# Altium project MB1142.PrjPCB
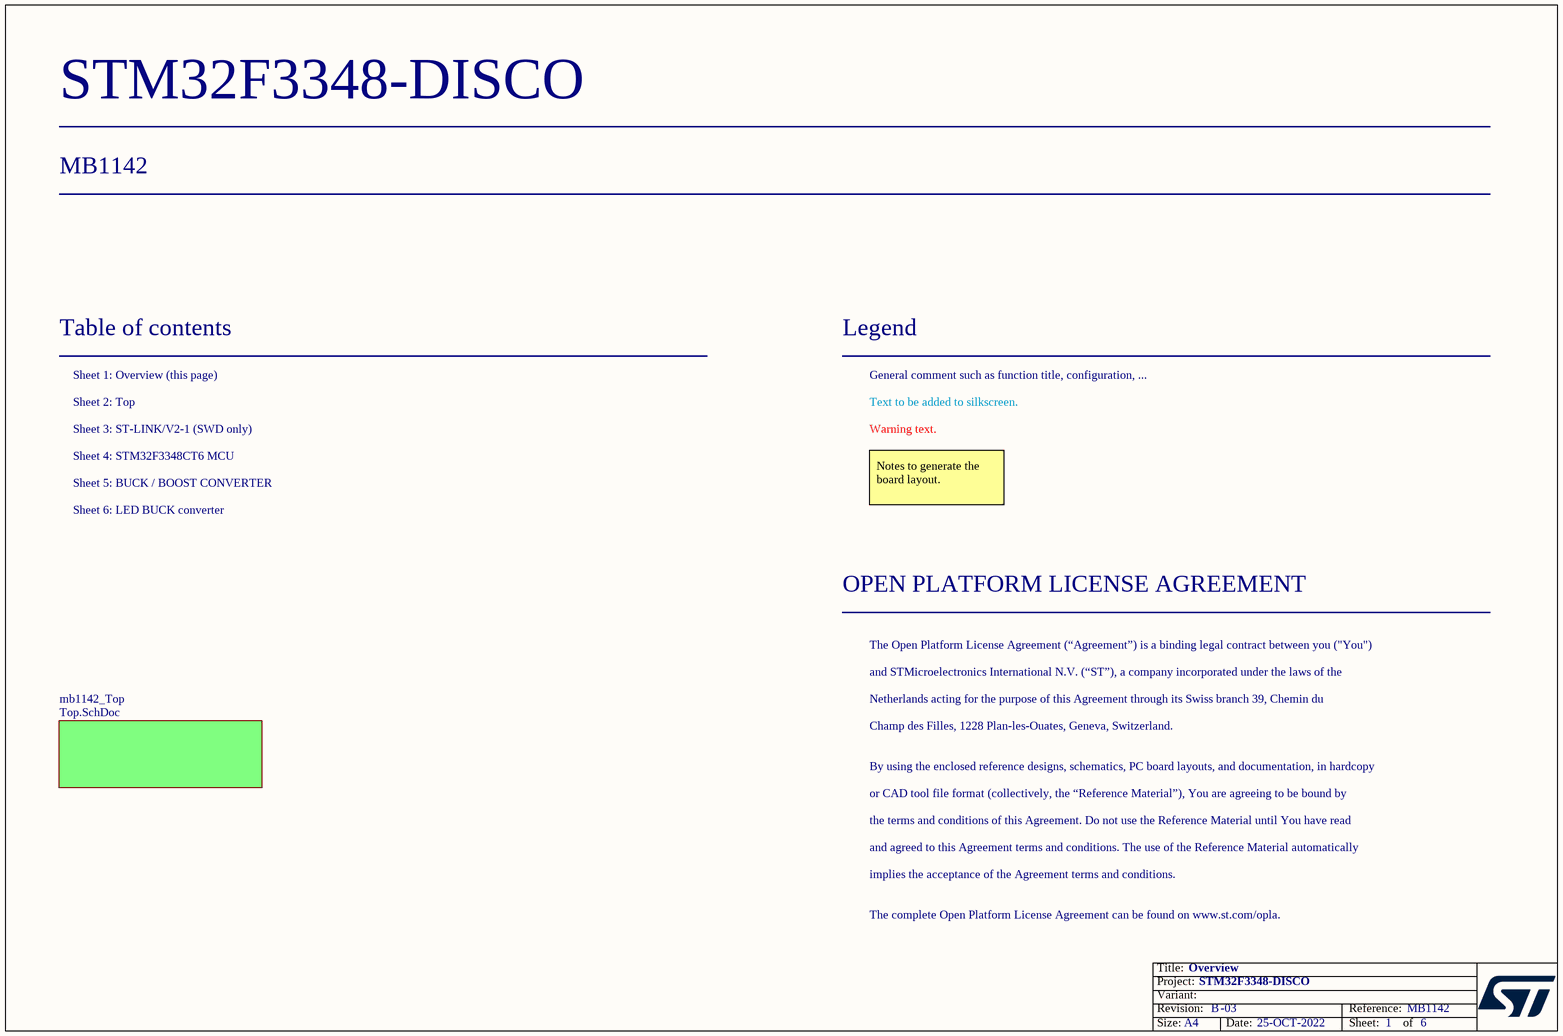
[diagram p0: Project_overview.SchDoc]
Board_Assembly_Revision: 03; Board_Document_Date: 25-OCT-2022; Board_Name: STM32F3348-DISCO; Board_PCB_Revision: B; Board_Reference: MB1142
6 sheets, 188 parts. Net scope: flat (ports and power ports of the same name join across sheets).
Sheets:
  Project_overview.SchDoc
    mb1142_Top = Top.SchDoc
      U_ST_LINK = ST_LINK_V2.SCHDOC
      U_STM32Fx = STM32Fx.SchDoc
      U_BUCK_BOOST = BUCK_BOOST.SchDoc
      U_BUCK_LED = BUCK_LED.SchDoc

## Sheet Project_overview.SchDoc: Overview
size A4; Date: Not used; ApprovedBy: Not used; CheckedBy: Not used; Author: Not used; CompanyName: STMicroelectronics; DrawnBy: Not used; Engineer: Not used; Organization: Not used; Address1: Not used; Address2: Not used; Address3: Not used; Address4: Not used; DocumentNumber: Not used; Revision: Not used; SheetNumber: 1; SheetTotal: 6

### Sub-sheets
mb1142_Top = Top.SchDoc: no entries

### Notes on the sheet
- Table of contents
- Sheet 1: Overview (this page)
- Legend
- General comment such as function title, configuration, ...
- Sheet 2: Top
- Sheet 3: ST-LINK/V2-1 (SWD only)
- Text to be added to silkscreen.
- Warning text.
- Sheet 4: STM32F3348CT6 MCU
- Sheet 6: LED BUCK converter
- Sheet 5: BUCK / BOOST CONVERTER
- Notes to generate the board layout.
- OPEN PLATFORM LICENSE AGREEMENT
- The Open Platform License Agreement (“Agreement”) is a binding legal contract between you ("You")
- and STMicroelectronics International N.V. (“ST”), a company incorporated under the laws of the
- Netherlands acting for the purpose of this Agreement through its Swiss branch 39, Chemin du
- Champ des Filles, 1228 Plan-les-Ouates, Geneva, Switzerland.
- By using the enclosed reference designs, schematics, PC board layouts, and documentation, in hardcopy
- or CAD tool file format (collectively, the “Reference Material”), You are agreeing to be bound by
- the terms and conditions of this Agreement. Do not use the Reference Material until You have read
- and agreed to this Agreement terms and conditions. The use of the Reference Material automatically
- implies the acceptance of the Agreement terms and conditions.
- The complete Open Platform License Agreement can be found on www.st.com/opla.

## Sheet Top.SchDoc: TOP
size A4; CompanyName: STM; DocumentNumber: MB1142; Revision: B-02; SheetNumber: 2; SheetTotal: 6; PageSetup: Record=PageOptions¦CenterHorizontal=True¦CenterVertical=True¦PrintScale=-0.03¦XCorrection=1.00¦YCorrection=1.00¦PrintKind=0¦BorderSize=5000000¦LeftOffset=0¦BottomOffset=0¦Orientation=2¦PaperLength=1000¦PaperWidth=1000¦Scale=100¦PaperSource=15¦PrintQuality=1200¦MediaType=1¦DitherType=10¦PaperKind=A4¦PrintScaleMode=1; Project: STM32F3348-DISCO
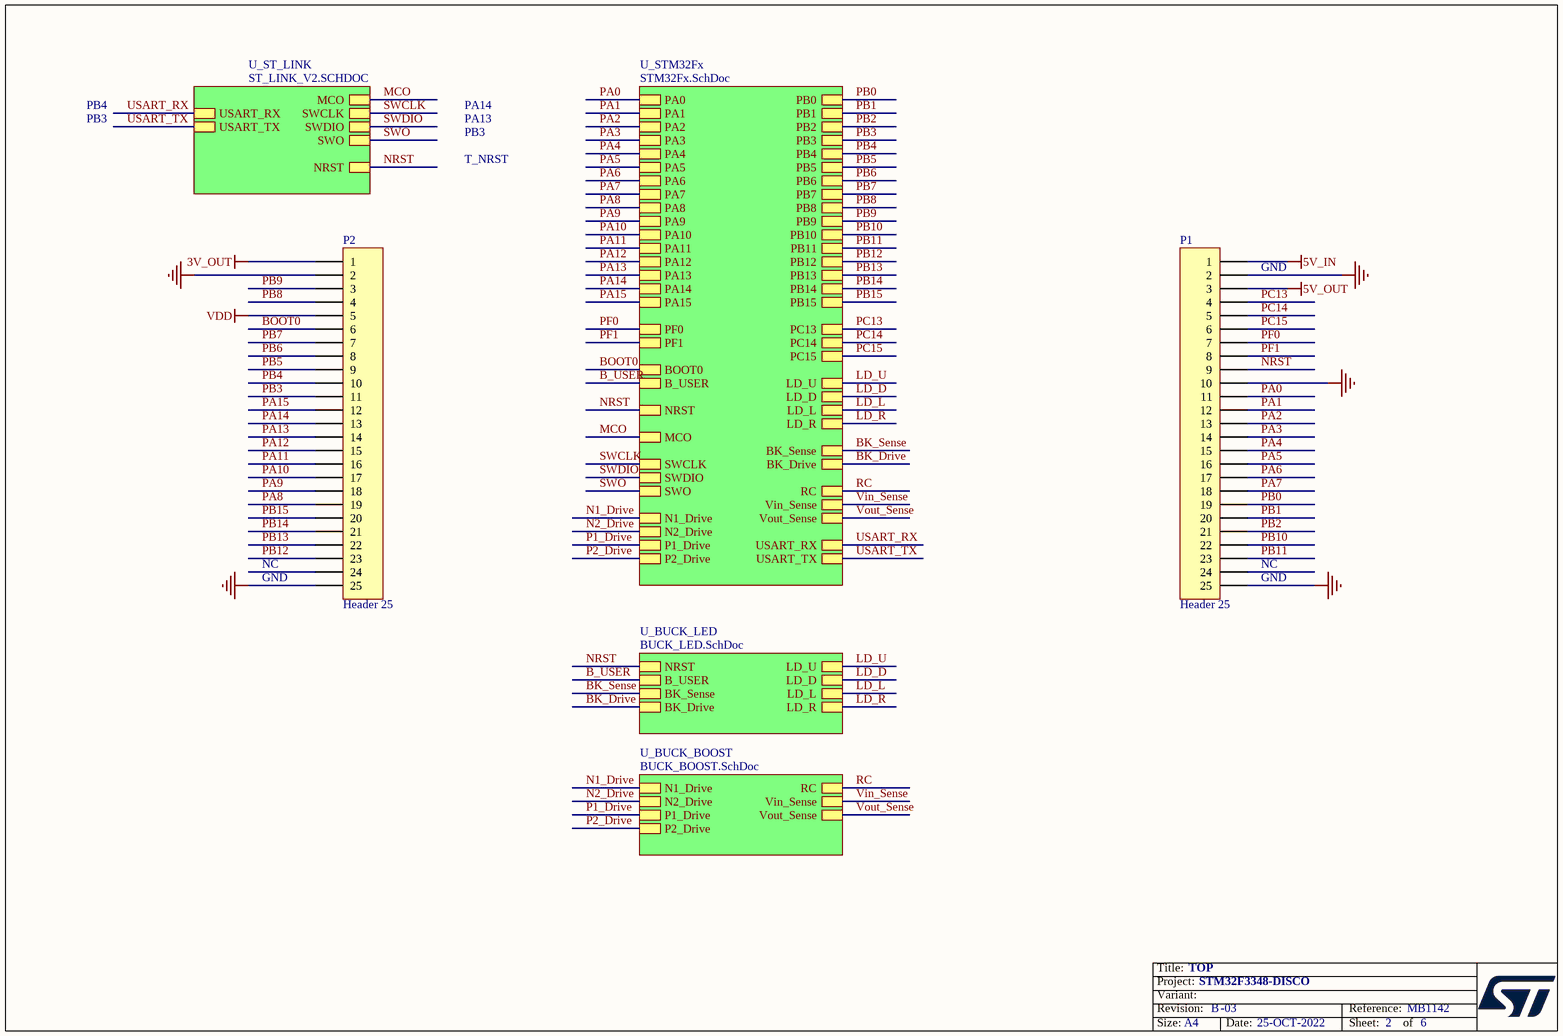
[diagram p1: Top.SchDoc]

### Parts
P1  Header 25  [HDR1X25]
P2  Header 25  [HDR1X25]

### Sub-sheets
U_BUCK_BOOST = BUCK_BOOST.SchDoc: N1_Drive, N2_Drive, Vout_Sense, P1_Drive, P2_Drive, Vin_Sense, RC
U_BUCK_LED = BUCK_LED.SchDoc: NRST, B_USER, BK_Sense, BK_Drive, LD_D, LD_U, LD_L, LD_R
U_ST_LINK = ST_LINK_V2.SCHDOC: NRST, MCO, SWDIO, SWCLK, SWO, USART_RX, USART_TX
U_STM32Fx = STM32Fx.SchDoc: PB8, BOOT0, NRST, PC15, PC14, PF1, PF0, MCO, PC13, PA0, PA1, PA2, PA3, PA4, PA5, PA6, PA7, PA8, PA9, PA10, PA11, PA12, PA13, PA14, PA15, PB0, PB1, PB2, PB3, PB4, PB5, PB6, PB7, PB9, PB10, PB11, PB12, PB13, PB14, PB15, B_USER, LD_D, LD_U, LD_L, LD_R, RC, Vout_Sense, P2_Drive, BK_Sense, Vin_Sense, BK_Drive, N1_Drive, P1_Drive, N2_Drive, SWCLK, SWDIO, SWO, USART_TX, USART_RX

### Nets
3V_OUT: P2.1  [project net 3V]
5V_IN: P1.1
5V_OUT: P1.3
GND: P1.2 P1.10 P1.25 P2.2 P2.25
VDD: P2.5
B_USER: sheet U_STM32Fx/B_USER, sheet U_BUCK_LED/B_USER
BK_Drive: sheet U_STM32Fx/BK_Drive, sheet U_BUCK_LED/BK_Drive
BK_Sense: sheet U_STM32Fx/BK_Sense, sheet U_BUCK_LED/BK_Sense
BOOT0: P2.6 ; sheet U_STM32Fx/BOOT0
LD_D: sheet U_STM32Fx/LD_D, sheet U_BUCK_LED/LD_D
LD_L: sheet U_STM32Fx/LD_L, sheet U_BUCK_LED/LD_L
LD_R: sheet U_STM32Fx/LD_R, sheet U_BUCK_LED/LD_R
LD_U: sheet U_STM32Fx/LD_U, sheet U_BUCK_LED/LD_U
MCO: sheet U_ST_LINK/MCO, sheet U_STM32Fx/MCO
N1_Drive: sheet U_STM32Fx/N1_Drive, sheet U_BUCK_BOOST/N1_Drive
N2_Drive: sheet U_STM32Fx/N2_Drive, sheet U_BUCK_BOOST/N2_Drive
NRST: P1.9 ; sheet U_ST_LINK/NRST, sheet U_STM32Fx/NRST, sheet U_BUCK_LED/NRST
P1_Drive: sheet U_STM32Fx/P1_Drive, sheet U_BUCK_BOOST/P1_Drive
P2_Drive: sheet U_STM32Fx/P2_Drive, sheet U_BUCK_BOOST/P2_Drive
PA0: P1.11 ; sheet U_STM32Fx/PA0
PA1: P1.12 ; sheet U_STM32Fx/PA1
PA2: P1.13 ; sheet U_STM32Fx/PA2
PA3: P1.14 ; sheet U_STM32Fx/PA3
PA4: P1.15 ; sheet U_STM32Fx/PA4
PA5: P1.16 ; sheet U_STM32Fx/PA5
PA6: P1.17 ; sheet U_STM32Fx/PA6
PA7: P1.18 ; sheet U_STM32Fx/PA7
PA8: P2.19 ; sheet U_STM32Fx/PA8
PA9: P2.18 ; sheet U_STM32Fx/PA9
PA10: P2.17 ; sheet U_STM32Fx/PA10
PA11: P2.16 ; sheet U_STM32Fx/PA11
PA12: P2.15 ; sheet U_STM32Fx/PA12
PA13: P2.14 ; sheet U_STM32Fx/PA13
PA14: P2.13 ; sheet U_STM32Fx/PA14
PA15: P2.12 ; sheet U_STM32Fx/PA15
PB0: P1.19 ; sheet U_STM32Fx/PB0
PB1: P1.20 ; sheet U_STM32Fx/PB1
PB2: P1.21 ; sheet U_STM32Fx/PB2
PB3: P2.11 ; sheet U_STM32Fx/PB3
PB4: P2.10 ; sheet U_STM32Fx/PB4
PB5: P2.9 ; sheet U_STM32Fx/PB5
PB6: P2.8 ; sheet U_STM32Fx/PB6
PB7: P2.7 ; sheet U_STM32Fx/PB7
PB8: P2.4 ; sheet U_STM32Fx/PB8
PB9: P2.3 ; sheet U_STM32Fx/PB9
PB10: P1.22 ; sheet U_STM32Fx/PB10
PB11: P1.23 ; sheet U_STM32Fx/PB11
PB12: P2.23 ; sheet U_STM32Fx/PB12
PB13: P2.22 ; sheet U_STM32Fx/PB13
PB14: P2.21 ; sheet U_STM32Fx/PB14
PB15: P2.20 ; sheet U_STM32Fx/PB15
PC13: P1.4 ; sheet U_STM32Fx/PC13
PC14: P1.5 ; sheet U_STM32Fx/PC14
PC15: P1.6 ; sheet U_STM32Fx/PC15
PF0: P1.7 ; sheet U_STM32Fx/PF0
PF1: P1.8 ; sheet U_STM32Fx/PF1
RC: sheet U_STM32Fx/RC, sheet U_BUCK_BOOST/RC
SWCLK: sheet U_ST_LINK/SWCLK, sheet U_STM32Fx/SWCLK
SWDIO: sheet U_ST_LINK/SWDIO, sheet U_STM32Fx/SWDIO
SWO: sheet U_ST_LINK/SWO, sheet U_STM32Fx/SWO
USART_RX: sheet U_ST_LINK/USART_RX, sheet U_STM32Fx/USART_RX
USART_TX: sheet U_ST_LINK/USART_TX, sheet U_STM32Fx/USART_TX
Vin_Sense: sheet U_STM32Fx/Vin_Sense, sheet U_BUCK_BOOST/Vin_Sense
Vout_Sense: sheet U_STM32Fx/Vout_Sense, sheet U_BUCK_BOOST/Vout_Sense

Not connected (* = marked no-connect by the designer): P1 24; P2 24

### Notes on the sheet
- PB4
- PA14
- PB3
- PA13
- T_NRST
- (near P1) GND
- GND
- NC
- (near P1) NC

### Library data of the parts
P1 P2 = Header 25: Header, 25-Pin

## Sheet ST_LINK_V2.SCHDOC: ST-LINK/V2-1 (SWD only)
size A4; CompanyName: STM; DocumentNumber: MB1142; Revision: B-02; SheetNumber: 3; SheetTotal: 6; PageSetup: Record=PageOptions¦CenterHorizontal=True¦CenterVertical=True¦PrintScale=1.00¦XCorrection=1.00¦YCorrection=1.00¦PrintKind=0¦BorderSize=5000000¦LeftOffset=0¦BottomOffset=0¦Orientation=2¦PaperLength=1000¦PaperWidth=1000¦Scale=100¦PaperSource=7¦PrintQuality=-4¦MediaType=1¦DitherType=10¦PaperKind=A4¦PrintScaleMode=1; Project: STM32F3348-DISCO
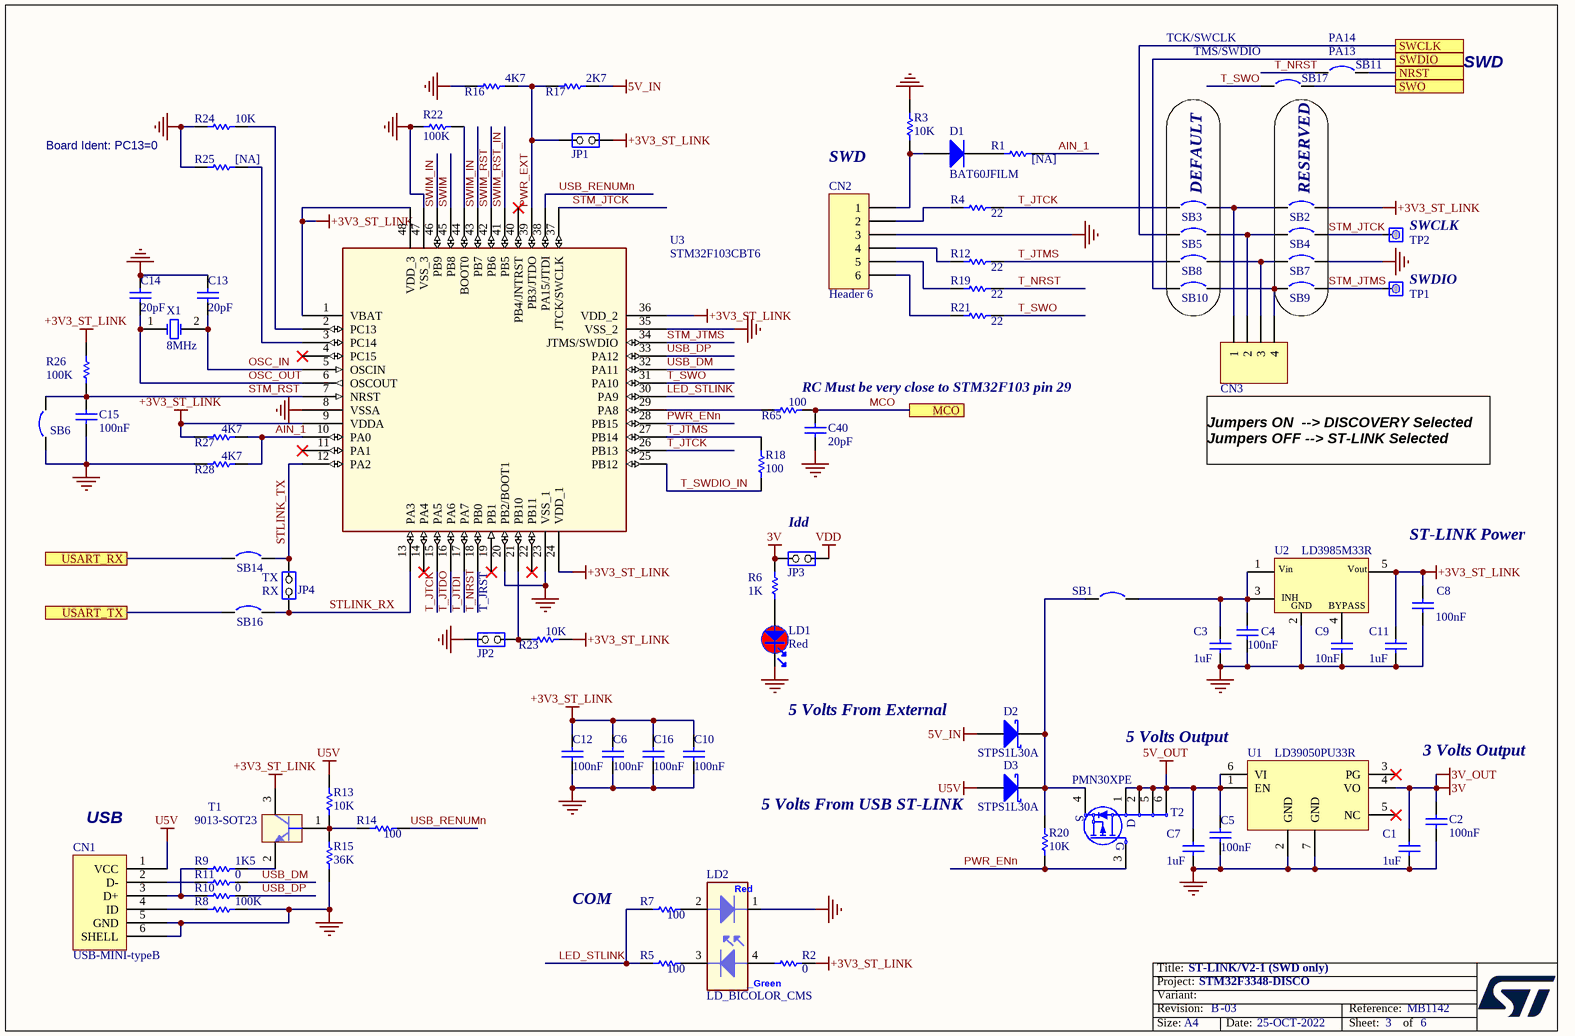
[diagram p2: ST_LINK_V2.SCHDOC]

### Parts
C1  1uF  [0603C]
C2  100nF  [0402C]
C3  1uF  [0603C]
C4  100nF  [0402C]
C5  100nF  [0402C]
C6  100nF  [0402C]
C7  1uF  [0603C]
C8  100nF  [0402C]
C9  10nF  [0603C]
C10  100nF  [0402C]
C11  1uF  [0603C]
C12  100nF  [0402C]
C13  20pF  [0402C]
C14  20pF  [0402C]
C15  100nF  [0402C]
C16  100nF  [0402C]
C40  20pF  [0402C]
CN1  USB-MINI-typeB  [USB-MINI-B-SMD]
CN2  Header 6  [HDR1X6]
CN3  Header 4  [Header 4]  (value not drawn)
D1  BAT60JFILM  [SOD323/A]
D2  STPS1L30A  [SMA]
D3  STPS1L30A  [SMA]
JP1  JP2  [SIP2/2.54]  (value not drawn)
JP2  Jumper2  [SIP2/2.54]  (value not drawn)
JP3  Jumper2  [SIP2/2.54]  (value not drawn)
JP4  Jumper2  [SIP2/2.54]  (value not drawn)
LD1  value Red  [LED_0603_RED]  (hidden comment: LED_red)
LD2  LD_BICOLOR_CMS  [HSMF-A201]
R1  [NA]  [0402R]
R2  0  [0402R]
R3  10K  [0402R]
R4  22  [0402R]
R5  100  [0402R]
R6  1K  [0402R]
R7  100  [0402R]
R8  100K  [0402R]
R9  1K5  [0402R]
R10  0  [0402R]
R11  0  [0402R]
R12  22  [0402R]
R13  10K  [0402R]
R14  100  [0402R]
R15  36K  [0402R]
R16  4K7  [0402R]
R17  2K7  [0402R]
R18  100  [0402R]
R19  22  [0402R]
R20  10K  [0402R]
R21  22  [0402R]
R22  100K  [0402R]
R23  10K  [0402R]
R24  10K  [0402R]
R25  [NA]  [0402R]
R26  100K  [0402R]
R27  4K7  [0402R]
R28  4K7  [0402R]
R65  100  [0402R]
SB1  Circuit Breaker  [JP2_SMD]  (value not drawn)
SB2  Circuit Breaker  [JP2_SMD]  (value not drawn)
SB3  Circuit Breaker  [JP2_SMD]  (value not drawn)
SB4  Circuit Breaker  [JP2_SMD]  (value not drawn)
SB5  Circuit Breaker  [JP2_SMD]  (value not drawn)
SB6  Circuit Breaker  [JP2_SMD]  (value not drawn)
SB7  Circuit Breaker  [JP2_SMD]  (value not drawn)
SB8  Circuit Breaker  [JP2_SMD]  (value not drawn)
SB9  Circuit Breaker  [JP2_SMD]  (value not drawn)
SB10  Circuit Breaker  [JP2_SMD]  (value not drawn)
SB11  Circuit Breaker  [JP2_SMD]  (value not drawn)
SB14  Circuit Breaker  [JP2_SMD]  (value not drawn)
SB16  Circuit Breaker  [JP2_SMD]  (value not drawn)
SB17  Circuit Breaker  [JP2_SMD]  (value not drawn)
T1  9013-SOT23  [SOT23]
T2  value PMN30XPE  [MOS_TSOP6_CASE-457_P095]  (hidden comment: PMN30XP)
TP1  Test point 1 pin with hole  [SIP1/2.54]  (value not drawn)
TP2  Test point 1 pin with hole  [SIP1/2.54]  (value not drawn)
U1  LD39050PU33R  [DFN6_3x3]
U2  LD3985M33R  [SOT-23-5L]
U3  STM32F103CBT6  [QFP48 7X7]
X1  8MHz  [XTAL1]

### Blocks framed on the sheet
DEFAULT: SB3 SB5 SB8 SB10
RESERVED: SB2 SB4 SB7 SB9

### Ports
MCO, NRST, SWCLK, SWDIO, SWO, USART_RX, USART_TX

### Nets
3V: C1.2 C2.2 JP3.1(COMMON) R6.2 U1.4(VO)  [also labelled 3V_OUT]
5V_IN: D2.1(A) R17.2
5V_OUT: C5.2 C7.2 T2.1(S) T2.2(S) T2.5(D) T2.6(D) U1.1(EN) U1.6(VI)
+3V3_ST_LINK: C6.2 C8.2 C10.2 C11.1 C12.2 C16.1 JP1.2(NO) R2.2 R23.2 R26.2 R27.1 SB2.2 T1.3(C) U2.5(Vout) U3.1(VBAT) U3.9(VDDA) U3.24(VDD_1) U3.36(VDD_2) U3.48(VDD_3)
GND: C1.1 C2.1 C3.1 C4.1 C5.1 C6.1 C7.1 C8.1 C9.1 C10.1 C11.2 C12.1 C13.1 C14.1 C15.1 C16.2 C40.2 CN1.5(GND) CN1.6(SHELL) CN2.3 JP2.1(COMMON) LD1.2 LD2.1 R3.2 R8.2 R15.1 R16.1 R22.1 R24.1 R25.1 R28.1 SB6.1 SB7.2 U1.2(GND) U1.7(GND) U2.2(GND) U3.8(VSSA) U3.20(PB2/BOOT1) U3.23(VSS_1) U3.35(VSS_2) U3.47(VSS_3)
U5V: CN1.1(VCC) D3.1(A) R13.2
VDD: JP3.2(NO)
AIN_1: R1.2 R27.2 R28.2 U3.10(PA0)
LED_STLINK: R5.1 R7.1 U3.30(PA9)
MCO: C40.1 R65.2 ; port MCO
NRST: SB11.2 ; port NRST
OSC_IN: C13.2 U3.5(OSCIN) X1.2(OSC2)
OSC_OUT: C14.2 U3.6(OSCOUT) X1.1(OSC1)
PA13: SB10.1 ; port SWDIO
PA14: SB5.1 ; port SWCLK
PB3: SB16.1 SB17.2 ; port SWO, port USART_TX
PB4: SB14.1 ; port USART_RX
PWR_ENn: R20.1 T2.3(G) U3.28(PB15)
PWR_EXT: JP1.1(COMMON) R16.2 R17.1 U3.39(PB3/JTDO)
STLINK_RX: JP4.1(COMMON) SB16.2 U3.13(PA3)
STLINK_TX: JP4.2(NO) SB14.2 U3.12(PA2)
STM_JTCK: SB4.2 TP2.1(COMMON) U3.37(JTCK/SWCLK)
STM_JTMS: SB9.2 TP1.1(COMMON) U3.34(JTMS/SWDIO)
STM_RST: C15.2 R26.1 SB6.2 U3.7(NRST)
SWIM: U3.45(PB8)
SWIM_IN: U3.43(PB7) U3.46(PB9)
SWIM_RST: U3.42(PB6)
SWIM_RST_IN: U3.41(PB5)
T_JTCK: R4.2 SB3.1 U3.15(PA5) U3.26(PB13)
T_JTDI: U3.17(PA7)
T_JTDO: U3.16(PA6)
T_JTMS: R12.2 R18.2 SB8.1 U3.27(PB14)
T_NRST: R19.2 SB11.1 U3.18(PB0)
T_SWDIO_IN: R18.1 U3.25(PB12)
T_SWO: R21.2 SB17.1 U3.31(PA10)
USB_DM: R11.2 U3.32(PA11)
USB_DP: R10.2 U3.33(PA12)
USB_RENUMn: R14.2 U3.38(PA15/JTDI)
NetC3_2: C3.2 C4.2 SB1.2 U2.1(Vin) U2.3(CE)
NetC9_2: C9.2 U2.4(BYPASS)
NetCN1_2: CN1.2(D-) R11.1
NetCN1_3: CN1.3(D+) R9.1 R10.1
NetCN1_4: CN1.4(ID) R8.1
NetCN2_1: CN2.1 D1.1(A) R3.1
NetCN2_2: CN2.2 R4.1
NetCN2_4: CN2.4 R12.1
NetCN2_5: CN2.5 R19.1
NetCN2_6: CN2.6 R21.1
NetCN3_1: CN3.1 SB2.1 SB3.2
NetCN3_2: CN3.2 SB4.1 SB5.2
NetCN3_3: CN3.3 SB7.1 SB8.2
NetCN3_4: CN3.4 SB9.1 SB10.2
NetD1_2: D1.2(K) R1.1
NetD2_2: D2.2(K) D3.2(K) R20.2 SB1.1 T2.4(S)
NetJP2_2: JP2.2(NO) R23.1 U3.21(PB10)
NetLD1_1: LD1.1 R6.1
NetLD2_2: LD2.2 R7.2
NetLD2_3: LD2.3 R5.2
NetLD2_4: LD2.4 R2.1
NetR9_2: R9.2 T1.2(E)
NetR13_1: R13.1 R14.1 R15.2 T1.1(B)
NetR22_2: R22.2 U3.44(BOOT0)
NetR24_2: R24.2 U3.2(PC13)
NetR25_2: R25.2 U3.3(PC14)
NetR65_1: R65.1 U3.29(PA8)

Not connected (* = marked no-connect by the designer): U1 3(PG)* 5(NC)*; U3 4(PC15)* 11(PA1)* 14(PA4)* 19(PB1)* 22(PB11)* 40(PB4/JNTRST)*

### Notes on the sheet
- TCK/SWCLK
- (near SB11) PA14
- (near SB17) TMS/SWDIO
- (near SB11) PA13
- SWD
- Board Ident: PC13=0
- (near TP2) SWCLK
- (near TP1) SWDIO
- (near R65) RC Must be very close to STM32F103 pin 29
- Jumpers ON  --> DISCOVERY Selected
  Jumpers OFF --> ST-LINK Selected
- TX
- Idd
- ST-LINK Power
- RX
- T_JRST
- 5 Volts From External
- (near U1) 5 Volts Output
- 3 Volts Output
- (near CN1) USB
- (near D3) 5 Volts From USB ST-LINK
- COM

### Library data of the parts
C1 C3 C7 C11 = Cap_1uF_X5R_10%_0603: Capacitor,1uF,16V,X5R,10%,0603,YAGEO; Manuf_Part_1: CC0603KRX5R7BB105
C2 C4-C6 C8 C10 C12 C15 C16 = Cap_100nF_X7R_10%_0402: Capacitor,100nF,16V,X7R,10%,0402,YAGEO; Manuf_Part_1: CC0402KRX7R7BB104
C9 = Cap_10nF_X7R_10%_0603: Capacitor,10nF,50V,X7R,10%,0603,YAGEO; Manuf_Part_1: CC0603KRX7R9BB103
C13 C14 = Cap_20pF_NPO_5%_0402: Capacitor,20pF,50V,NPO,5%,0402,YAGEO; Order: CC0402JRNPO9BN200
C40 = Cap_20pF_NPO_5%_0402: Capacitor,20pF,50V,NPO,5%,0402,YAGEO; Order: CC0402JRNPO9BN200; Fitted: NO
CN1 = USB-MINI-typeB connector: Manuf_Part_1: 5075BMR-05-SM; Manuf_Part_2: 218205M1110T; Manuf_2: lyconn
CN2 = Header 6: Header, 6-Pin
CN3 = Header 4: Header, 4-Pin
D1 = BAT60JFILM: Manuf_1: STM; Provided: ST; ECCN_US/EU: EAR99/NEC; Ref St: 9151097
D2 D3 = STPS1L30A: Low Drop power Schottky rectifier; Manuf_1: STM; Provided: ST; Ref St: xxxxxxxx; ECCN_US/EU: EAR99/NEC
JP1 = JP2: Fitted: NO
JP2 JP4 = Jumper2: Fitted: NO
LD1 = MCD-02899: LED, Red, 2V35, 20mA, 0603; Part_Type: Display; Part_Preference: Recommended; Manufacturer: EVERLIGHT; Manufacturer_Part_Number: 19-213/R6C-AP1Q2B/5T; Full_Alternate_Internal_Part_Number: MCD-00049; Component_Country_Of_Origin: China; ShowFields: YES; ID: 5015
LD2 = LD_BICOLOR_CMS: Bicolor Led; Manuf_Part_1: HSMF-A201-A00J1; Manuf_1: Avago Technologies; Manuf_2: everluck; Manuf_Part_2: LE-RGW35280; Ref St: xxxxxx; ECCN_US/EU: EAR99/NEC
R1 R25 = Resistor_ST: Resistor 0402 / 0603 / 0805; Fitted: NO
R2-R13 R16-R24 R26-R28 R65 = Resistor_ST: Resistor 0402 / 0603 / 0805
R14 R15 = Resistor_ST: Resistor 0402 / 0603 / 0805; Value: 10K
SB1 SB3 SB5 SB8 SB10 SB11 SB14 SB16 = Circuit Breaker: Solder: YES
SB2 SB4 SB6 SB7 SB9 SB17 = Circuit Breaker: Solder: NO
T1 = 9013-SOT23: NPN Bipolar Transistor; Manuf_1: NXP; Manuf_Part_1: BSR14; Order: 1081310; ECCN_US/EU: EAR99/NEC
T2 = MCD-03170: Transistor, MOSFET, P-CH, -20V, 7A, SOT457; Part_Preference: Recommended; Manufacturer: NEXPERIA; Partial_Alternate_Internal_Part_Number: MCD-01926; Component_Country_Of_Origin: China°; ShowFields: YES; ID: 5286
TP1 TP2 = TP1: Test Point; Fitted: NO
U1 = LD39050P: Ultra low drop-low , 500 mA low quiescent current; Manuf_1: STM; Provided: ST; ECCN_US/EU: EAR99/NEC; Ref St: xxxxxxxx
U2 = LD3985M33R: Ultra low drop-low noise BiCMOS voltage, regulators low ESR capacitors compatible; Manuf_1: STM; Provided: ST; Ref St: 9176161; ECCN_US/EU: EAR99/NEC
U3 = STM32F103CBT6: Medium-density performance line ARM-based 32-bit MCU with 128KB Flash; Manuf_1: STM; Ref St: xxxxxxxx; Provided: ST; ECCN_US/EU: 3A991A2/NEC
X1 = XTAL_8MHZ_20PPM: Crystal Oscillator,8Mhz,20PF,20PPM,-10-70 degree,DIP,HC-49S; Manuf_Part_1: HC-49S-C20QSA-8.000MHZ; ECCN_US/EU: EAR99/NEC

## Sheet STM32Fx.SchDoc: STM32F3348CT6 MCU
size A4; CompanyName: STM; DocumentNumber: MB1142; Revision: B-02; SheetNumber: 4; SheetTotal: 6; PageSetup: Record=PageOptions¦CenterHorizontal=True¦CenterVertical=True¦PrintScale=1.00¦XCorrection=1.00¦YCorrection=1.00¦PrintKind=0¦BorderSize=5000000¦LeftOffset=0¦BottomOffset=0¦Orientation=2¦PaperLength=1000¦PaperWidth=1000¦Scale=100¦PaperSource=7¦PrintQuality=-4¦MediaType=1¦DitherType=10¦PaperKind=A4¦PrintScaleMode=1; Project: STM32F3348-DISCO
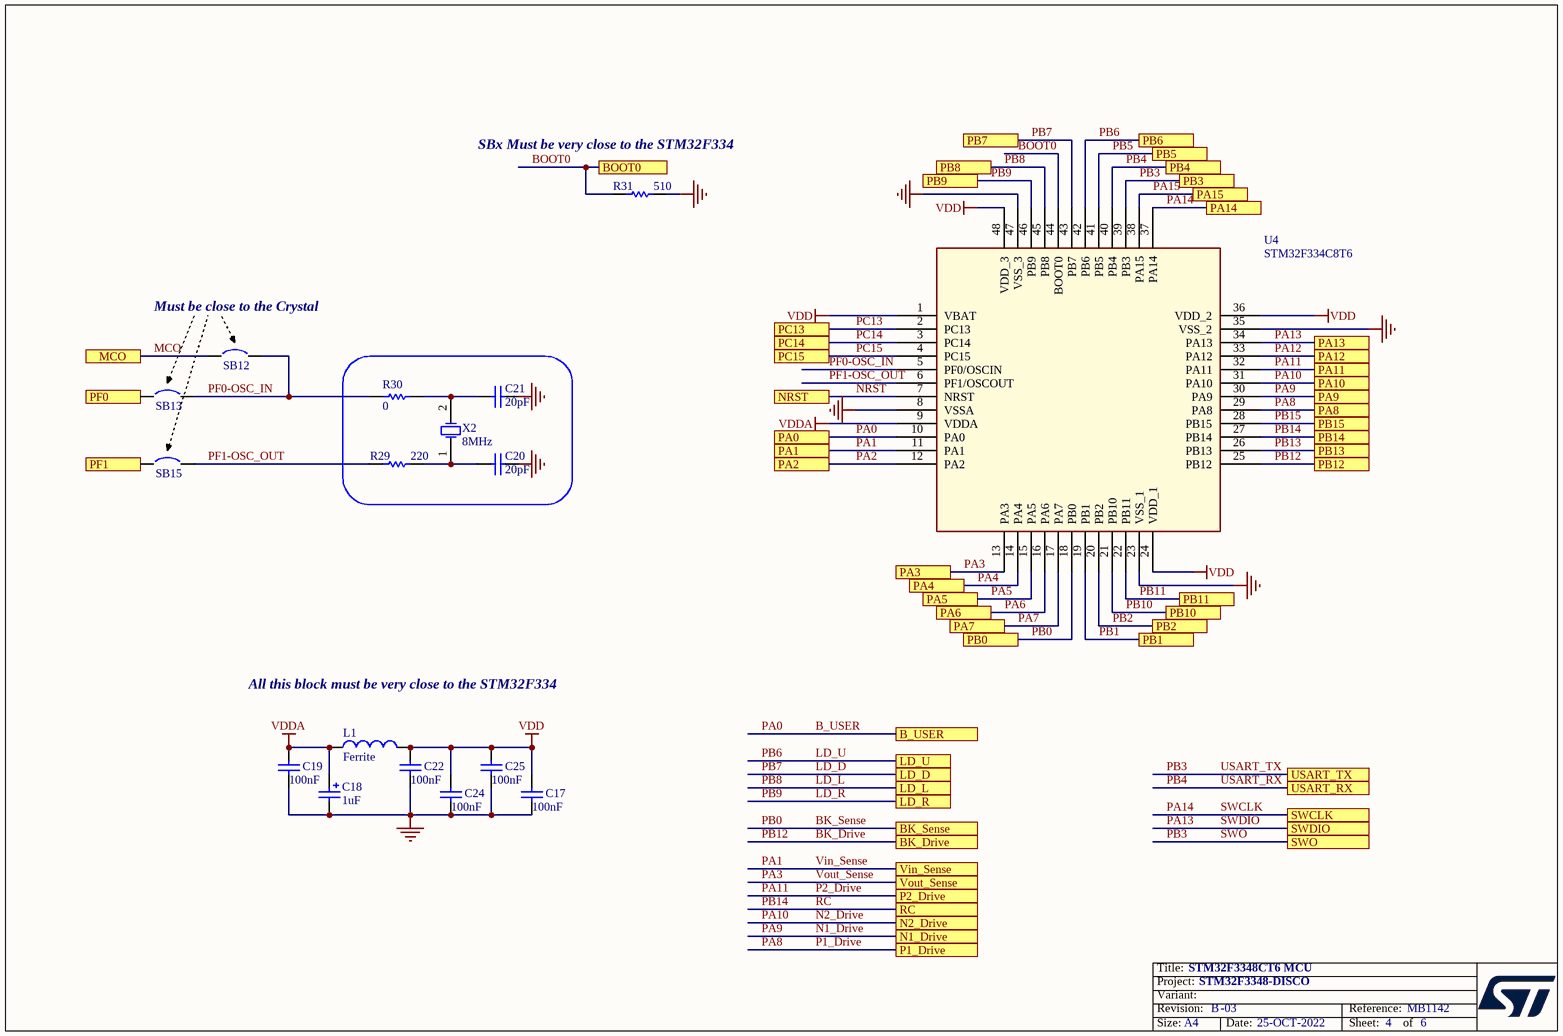
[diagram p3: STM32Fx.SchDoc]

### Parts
C17  100nF  [0402C]
C18  1uF  [TAN-A]
C19  100nF  [0402C]
C20  20pF  [0402C]
C21  20pF  [0402C]
C22  100nF  [0402C]
C24  100nF  [0402C]
C25  100nF  [0402C]
L1  Ferrite  [0603L]
R29  220  [0402R]
R30  0  [0402R]
R31  510  [0402R]
SB12  Circuit Breaker  [JP2_SMD]  (value not drawn)
SB13  Circuit Breaker  [JP2_SMD]  (value not drawn)
SB15  Circuit Breaker  [JP2_SMD]  (value not drawn)
U4  STM32F334C8T6  [QFP48 7X7]
X2  8MHz  [XTAL1]

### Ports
B_USER, BK_Drive, BK_Sense, BOOT0, LD_D, LD_L, LD_R, LD_U, MCO, N1_Drive, N2_Drive, NRST, P1_Drive, P2_Drive, PA0, PA1, PA2, PA3, PA4, PA5, PA6, PA7, PA8, PA9, PA10, PA11, PA12, PA13, PA14, PA15, PB0, PB1, PB2, PB3, PB4, PB5, PB6, PB7, PB8, PB9, PB10, PB11, PB12, PB13, PB14, PB15, PC13, PC14, PC15, PF0, PF1, RC, SWCLK, SWDIO, SWO, USART_RX, USART_TX, Vin_Sense, Vout_Sense

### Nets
GND: C17.1 C18.2 C19.1 C20.1 C21.1 C22.1 C24.1 C25.2 R31.2 U4.8(VSSA) U4.23(VSS_1) U4.35(VSS_2) U4.47(VSS_3)
VDD: C17.2 C22.2 C24.2 C25.1 L1.2 U4.1(VBAT) U4.24(VDD_1) U4.36(VDD_2) U4.48(VDD_3)
VDDA: C18.1 C19.2 L1.1 U4.9(VDDA)
B_USER: U4.10(PA0) ; port PA0, port B_USER  [also labelled PA0]
BK_Drive: U4.25(PB12) ; port PB12, port BK_Drive  [also labelled PB12]
BK_Sense: U4.18(PB0) ; port PB0, port BK_Sense  [also labelled PB0]
BOOT0: R31.1 U4.44(BOOT0) ; port BOOT0
LD_D: U4.43(PB7) ; port PB7, port LD_D  [also labelled PB7]
LD_L: U4.45(PB8) ; port PB8, port LD_L  [also labelled PB8]
LD_R: U4.46(PB9) ; port PB9, port LD_R  [also labelled PB9]
LD_U: U4.42(PB6) ; port PB6, port LD_U  [also labelled PB6]
MCO: SB12.1 ; port MCO
N1_Drive: U4.30(PA9) ; port PA9, port N1_Drive  [also labelled PA9]
N2_Drive: U4.31(PA10) ; port PA10, port N2_Drive  [also labelled PA10]
NRST: U4.7(NRST) ; port NRST
P1_Drive: U4.29(PA8) ; port PA8, port P1_Drive  [also labelled PA8]
P2_Drive: U4.32(PA11) ; port PA11, port P2_Drive  [also labelled PA11]
PA1: U4.11(PA1) ; port PA1, port Vin_Sense  [also labelled Vin_Sense]
PA2: U4.12(PA2) ; port PA2
PA3: U4.13(PA3) ; port PA3, port Vout_Sense  [also labelled Vout_Sense]
PA4: U4.14(PA4) ; port PA4
PA5: U4.15(PA5) ; port PA5
PA6: U4.16(PA6) ; port PA6
PA7: U4.17(PA7) ; port PA7
PA12: U4.33(PA12) ; port PA12
PA13: U4.34(PA13) ; port PA13, port SWDIO  [also labelled SWDIO]
PA14: U4.37(PA14) ; port PA14, port SWCLK  [also labelled SWCLK]
PA15: U4.38(PA15) ; port PA15
PB1: U4.19(PB1) ; port PB1
PB2: U4.20(PB2) ; port PB2
PB3: U4.39(PB3) ; port PB3, port USART_TX, port SWO  [also labelled SWO, USART_TX]
PB4: U4.40(PB4) ; port PB4, port USART_RX  [also labelled USART_RX]
PB5: U4.41(PB5) ; port PB5
PB10: U4.21(PB10) ; port PB10
PB11: U4.22(PB11) ; port PB11
PB13: U4.26(PB13) ; port PB13
PB14: U4.27(PB14) ; port PB14, port RC  [also labelled RC]
PB15: U4.28(PB15) ; port PB15
PC13: U4.2(PC13) ; port PC13
PC14: U4.3(PC14) ; port PC14
PC15: U4.4(PC15) ; port PC15
PF0-OSC_IN: R30.1 SB12.2 SB13.2 U4.5(PF0/OSCIN)
PF1-OSC_OUT: R29.2 SB15.2 U4.6(PF1/OSCOUT)
NetC20_2: C20.2 R29.1 X2.1(OSC1)
NetC21_2: C21.2 R30.2 X2.2(OSC2)
NetSB13_1: SB13.1 ; port PF0
NetSB15_1: SB15.1 ; port PF1

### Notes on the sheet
- (near R31) SBx Must be very close to the STM32F334
- (near SB12) Must be close to the Crystal
- All this block must be very close to the STM32F334

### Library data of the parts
C17 C19 C22 C24 C25 = Cap_100nF_X7R_10%_0402: as C2 on sheet ST_LINK_V2
C18 = Cap_1uF_POL_10%_TANA: Polarized Capacitor,1uF,16V,10%,typeA,AVX; Manuf_Part_1: TAJA105K016R
C20 C21 = Cap_20pF_NPO_5%_0402: as C40 on sheet ST_LINK_V2
L1 = BEAD_600R_350MA_0603: Bead,600R,350mA,0603,FCM1608KF-601T03,Tai-tech; Manuf_2: TDK; Manuf_Part_2: MPZ1608S300A; Value: 100uH; Comment_1: bead,30R,5A,0603,MPZ1608S300A,TDK
R29 = Res1: Resistor; Fitted: NO
R30 = Res_0_0402: Resistor,0,0402; Fitted: NO
R31 = Resistor_ST: Resistor 0402 / 0603 / 0805; Value: 10K
SB12 = Circuit Breaker: Solder: YES
SB13 SB15 = Circuit Breaker: Solder: NO
U4 = STM32F334C8T6: Medium-density performance line ARM-based 32-bit MCU with 64KB Flash and High Resolution Timer; Manuf_1: STM; Ref St: xxxxxxxxx; Provided: ST; ECCN_US/EU: 3A991A2/NEC
X2 = XTAL: Crystal Oscillator,8Mhz,20PF,20PPM,-10-70 degree,DIP,HC-49S; Manuf_Part_1: 9SL8000020AFXHF0; ECCN_US/EU: EAR99/NEC

## Sheet BUCK_BOOST.SchDoc: BUCK / BOOST CONVERTER
size A4; CompanyName: STM; DocumentNumber: MB1142; Revision: B-02; SheetNumber: 5; SheetTotal: 6; PageSetup: Record=PageOptions¦CenterHorizontal=True¦CenterVertical=True¦PrintScale=1.00¦XCorrection=1.00¦YCorrection=1.00¦PrintKind=0¦BorderSize=5000000¦LeftOffset=0¦BottomOffset=0¦Orientation=2¦PaperLength=1000¦PaperWidth=1000¦Scale=100¦PaperSource=7¦PrintQuality=-4¦MediaType=1¦DitherType=10¦PaperKind=A4¦PrintScaleMode=1; Project: STM32F3348-DISCO
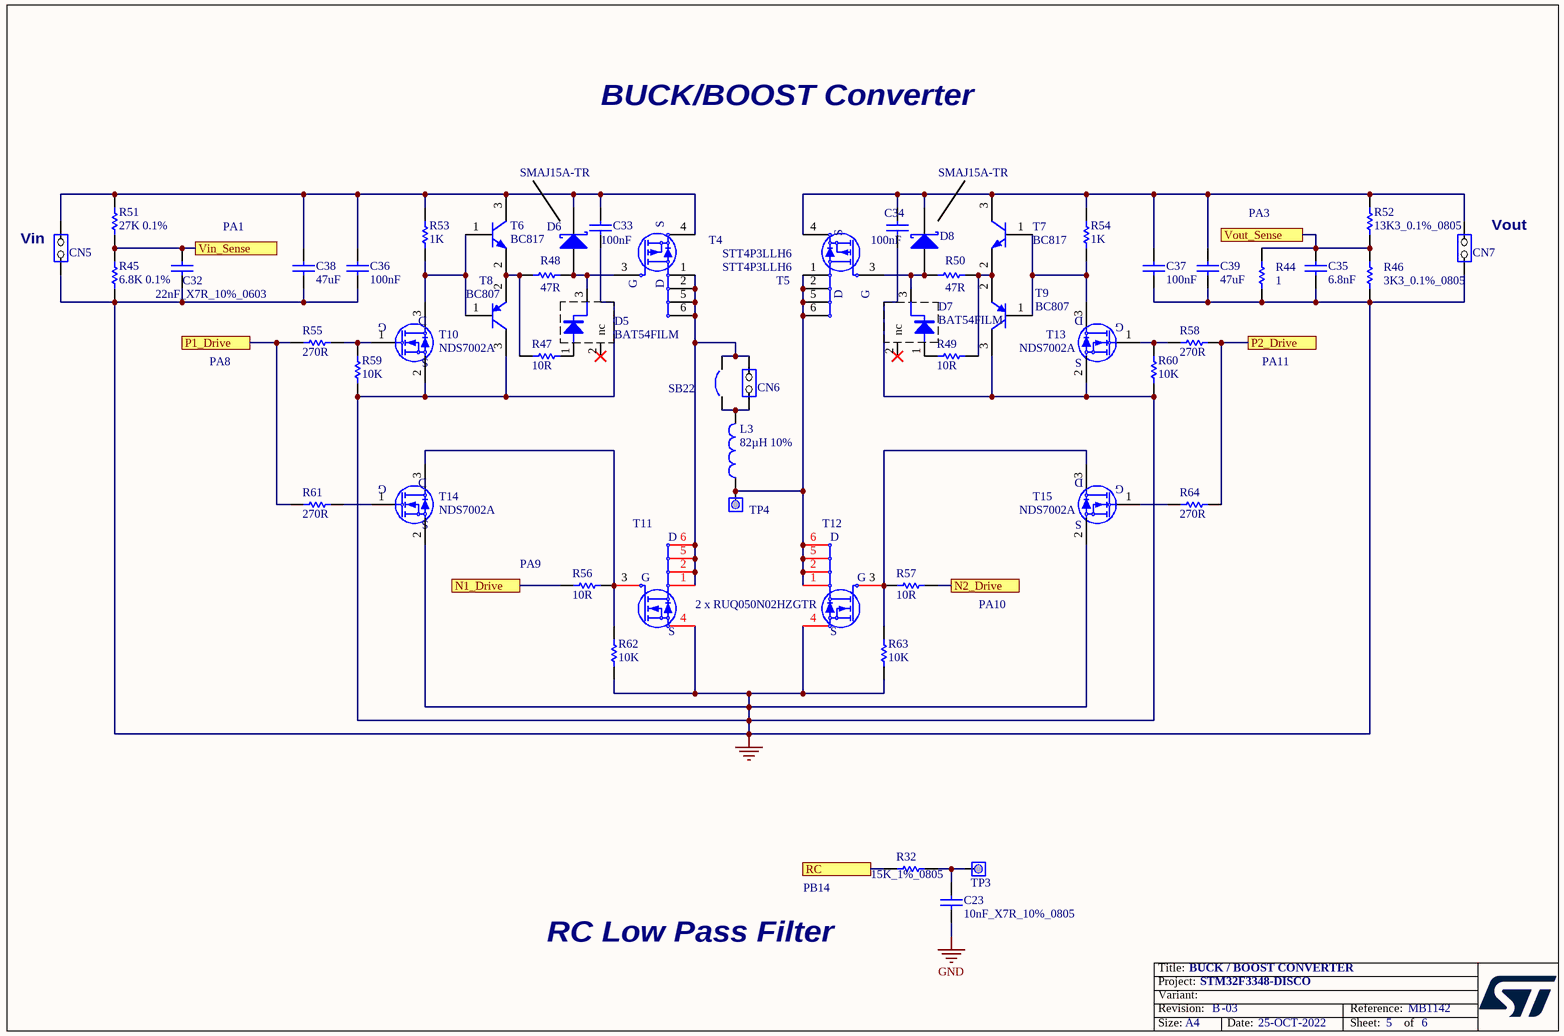
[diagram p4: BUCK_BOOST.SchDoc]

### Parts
C23  10nF_X7R_10%_0805  [0805C]
C32  22nF_X7R_10%_0603  [0603C]
C33  100nF  [0805C]
C34  100nF  [0805C]
C35  6.8nF  [0603C]
C36  100nF  [0805C]
C37  100nF  [0805C]
C38  47uF  [1206C]
C39  47uF  [1206C]
CN5  Jumper2  [SIP2/2.54]  (value not drawn)
CN6  JP2  [SIP2/2.54]  (value not drawn)
CN7  Jumper2  [SIP2/2.54]  (value not drawn)
D5  BAT54FILM  [SOT23]
D6  value SMAJ15A-TR  [DIO_SMA_1A_2K]  (hidden comment: ESD-TRANSIL-SMAJ_1A_2K)
D7  BAT54FILM  [SOT23]
D8  value SMAJ15A-TR  [DIO_SMA_1A_2K]  (hidden comment: ESD-TRANSIL-SMAJ_1A_2K)
L3  82µH 10%  [PSI054T]
R32  15K_1%_0805  [0805R]
R44  1  [1206R]
R45  6.8K 0.1%  [0805R]
R46  3K3_0.1%_0805  [0805R]
R47  10R  [0805]
R48  47R  [0805R]
R49  10R  [0805]
R50  47R  [0805]
R51  27K 0.1%  [0805]
R52  13K3_0.1%_0805  [0805R]
R53  1K  [0805R]
R54  1K  [0805]
R55  270R  [0805R]
R56  10R  [0805]
R57  10R  [0805]
R58  270R  [0805]
R59  10K  [0805]
R60  10K  [0805]
R61  270R  [0805R]
R62  10K  [0805]
R63  10K  [0805]
R64  270R  [0805]
SB22  Circuit Breaker  [JP2_SMD]  (value not drawn)
T4  STT4P3LLH6  [SOT23-6L]
T5  STT4P3LLH6  [SOT23-6L]
T6  BC817  [SOT23]
T7  BC817  [SOT23]
T8  BC807  [SOT23]
T9  BC807  [SOT23]
T10  NDS7002A  [SOT23]
T11  value 2 x RUQ050N02HZGTR  [MOS_TSMT6_SOT-457T_SC95]
T12  (no value)  [MOS_TSMT6_SOT-457T_SC95]
T13  NDS7002A  [SOT23]
T14  NDS7002A  [SOT23]
T15  NDS7002A  [SOT23]
TP3  Test point 1 pin with hole  [SIP1/2.54]  (value not drawn)
TP4  Test point 1 pin with hole  [SIP1/2.54]  (value not drawn)

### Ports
N1_Drive, N2_Drive, P1_Drive, P2_Drive, RC, Vin_Sense, Vout_Sense

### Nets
GND: C23.1 C32.1 C33.1 C34.1 C35.1 C36.1 C37.1 C38.1 C39.1 CN5.1(COMMON) CN7.1(COMMON) R44.1 R45.1 R46.1 R59.1 R60.1 R62.1 R63.1 T8.3(C) T9.3(C) T10.2(S) T11.4 T12.4 T13.2(S) T14.2(S) T15.2(S)
N1_Drive: R56.1 ; port N1_Drive
N2_Drive: R57.2 ; port N2_Drive
P1_Drive: R55.1 R61.1 ; port P1_Drive
P2_Drive: R58.2 R64.2 ; port P2_Drive
PA1: C32.2 R45.2 R51.1 ; port Vin_Sense
PA3: C35.2 R44.2 R46.2 R52.2 ; port Vout_Sense
PB14: R32.1 ; port RC
NetC23_2: C23.2 R32.2 TP3.1(COMMON)
NetC33_2: C33.2 C36.2 C38.2 CN5.2(NO) D6.2(K) R51.2 R53.2 T4.4(S) T6.3(C)
NetC34_2: C34.2 C37.2 C39.2 CN7.2(NO) D8.2(K) R52.1 R54.2 T5.4(S) T7.3(C)
NetCN6_1: CN6.1(COMMON) L3.2 SB22.1
NetCN6_2: CN6.2(NO) SB22.2 T4.1(S) T4.2(S) T4.5(D) T4.6(D) T11.1 T11.2 T11.5 T11.6
NetD5_1: D5.1 R47.2
NetD5_3: D5.3 D6.1(A) R48.2 T4.3(G)
NetD7_1: D7.1 R49.1
NetD7_3: D7.3 D8.1(A) R50.1 T5.3(G)
NetL3_1: L3.1 T5.1(S) T5.2(S) T5.5(D) T5.6(D) T12.1 T12.2 T12.5 T12.6 TP4.1(COMMON)
NetR47_1: R47.1 R48.1 T6.2(E) T8.2(E)
NetR49_2: R49.2 R50.2 T7.2(E) T9.2(E)
NetR53_1: R53.1 T6.1(B) T8.1(B) T10.3(D)
NetR54_1: R54.1 T7.1(B) T9.1(B) T13.3(D)
NetR55_2: R55.2 R59.2 T10.1(G)
NetR56_2: R56.2 R62.2 T11.3 T14.3(D)
NetR57_1: R57.1 R63.2 T12.3 T15.3(D)
NetR58_1: R58.1 R60.2 T13.1(G)
NetR61_2: R61.2 T14.1(G)
NetR64_1: R64.1 T15.1(G)

Not connected (* = marked no-connect by the designer): D5 2(nc)*; D7 2(nc)*

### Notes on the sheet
- BUCK/BOOST Converter
- (near CN5) Vin
- PA1
- PA3
- (near CN7) Vout
- PA8
- PA11
- (near R56) PA9
- PA10
- PB14
- RC Low Pass Filter

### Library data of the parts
C23 = Cap_10nF_X7R_10%_0805: Capacitor,10nF,50V,X7R,10%,0805,YAGEO; Manuf_Part_1: C0805C103K5RACTU
C32 = Cap_22nF_X7R_10%_0603: Capacitor,22nF,50V,X7R,10%,0603,YAGEO; Manuf_Part_1: CC0603KRX7R9BB223
C33 C34 C36 C37 = Cap_100nF_X7R_10%_0805: Capacitor,100nF,50V,X7R,10%,0805,YAGEO; Order: CC0805KKX7R9BB104
C35 = Cap_6.8nF_X7R_10%_0603: Capacitor,6.8nF,50V,X7R,10%,0603,YAGEO; Manuf_Part_1: CC0603KRX7R9BB682; Fitted: NO
C38 C39 = Cap_47uF_X5R_10%_1206: Capacitor,47uF,25V, X5R,10%,1206,TDK; Manuf_Part_1: C3216X5R1E476M160AC; Order: 2354130
CN6 = JP2: Fitted: NO
D5 D7 = BAT54FILM: Schottky Single diode; Manuf_1: STM; Provided: ST; Ref St: xxxxxxxx; ECCN_US/EU: EAR99/NEC
D6 D8 = MCD-01522: Transil unidirectional diode Vrm=15V, Vbr=16.7V(1mA), Vcl=32.5V(71A), SMA; BMS_Part_Number: 9151113; Part_Preference: Recommended; Manufacturer: STMICROELECTRONICS; Manufacturer_HQ_COO: EU; Component_Country_Of_Origin: China; ShowFields: YES; ID: 3622
L3 = Ind_82µH_0.65A_10%: Power Inductor 82µH 0,65A; Manuf_Part_1: PSI054T-820MS-11; Manuf_1: CYNTEC; Manuf_Part_2: A916CY-820M; Manuf_2: TOKO; Order_2: 752-1406
R32 = Res_15K_1%_0805: Resistor,15K,0805,1%,YAGEO; Manuf_Part_1: RC0805FR-0715KL
R44 = Res_1_1%_1206: Resistor,1,1206,1%,VISHAY; Manuf_Part_1: CRCW12061R00FKEA; Order: 1653087; Fitted: NO
R45 R47-R51 R53-R63 = RES SMD 0805 4R7 150V  0.125W: 0805 4R7 150V  0.125W; Manufacturer: PANASONIC; Manufacturer P/N: ERJ6GEYJ4R7V; Tolerance: 1%
R46 = Res_3K3_0.1%_0805: Resistor,3K3,0805,0.1%,YAGEO; Manuf_Part_1: RT0805BRD073K3L
R52 = Res_13K3_0.1%_0805: Resistor,13K3,0805,0.1%,YAGEO; Manuf_Part_1: RT0805BRD0713K3L
R64 = RES SMD 0805 4R7 150V  0.125W: 0805 4R7 150V  0.125W; Manufacturer: PANASONIC; Manufacturer P/N: ERJ6GEYJ4R7V; Tolerance: 1%; Fitted: NO
SB22 = Circuit Breaker: Solder: YES
T4 T5 = STT4P3LLH6: STripFET VI DeepGATE Power MOSFET, P-CHANNEL 30 V, 0.04, 4 A - SOT23-6L; Manuf_1: STM; Provided: ST; Ref St: xxxxxxxx; ECCN_US/EU: EAR99/NEC
T6 T7 = BC817: 45 V, 500 mA, NPN General-purpose Transistor SOT-23; Manuf_1: NXP; Order: 1081223; ECCN_US/EU: EAR99/NEC
T8 T9 = BC807: 45 V, 500 mA, PNP General-purpose Transistor SOT-23; Manuf_1: NXP; Order: 1081219; ECCN_US/EU: EAR99/NEC
T10 T13 T14 = NDS7002A: Power MOSFET, N-channel 60 V, 1.7, 0.28 A, SOT23; Manuf_1: FAIRCHILD; Ref St: xxxxxxxx; ECCN_US/EU: EAR99/NEC
T11 T12 = MCD-03073: Transistor, MOSFET, N-CH, 20V, 5A, TSMT6; Part_Preference: Recommended; Manufacturer: ROHM SEMICONDUCTOR; Manufacturer_Part_Number: RUQ050N02HZGTR; Component_Country_Of_Origin: Thailand°; ShowFields: YES; ID: 5189
T15 = NDS7002A: Power MOSFET, N-channel 60 V, 1.7, 0.28 A, SOT23; Manuf_1: FAIRCHILD; Ref St: xxxxxxxx; ECCN_US/EU: EAR99/NEC; Fitted: NO
TP3 TP4 = TP1: Test Point; Fitted: NO

## Sheet BUCK_LED.SchDoc: LED BUCK converter
size A4; CompanyName: STM; DocumentNumber: MB1142; Revision: B-02; SheetNumber: 6; SheetTotal: 6; PageSetup: Record=PageOptions¦CenterHorizontal=True¦CenterVertical=True¦PrintScale=1.00¦XCorrection=1.00¦YCorrection=1.00¦PrintKind=0¦BorderSize=5000000¦LeftOffset=0¦BottomOffset=0¦Orientation=2¦PaperLength=1000¦PaperWidth=1000¦Scale=100¦PaperSource=7¦PrintQuality=-4¦MediaType=1¦DitherType=10¦PaperKind=A4¦PrintScaleMode=1; Project: STM32F3348-DISCO
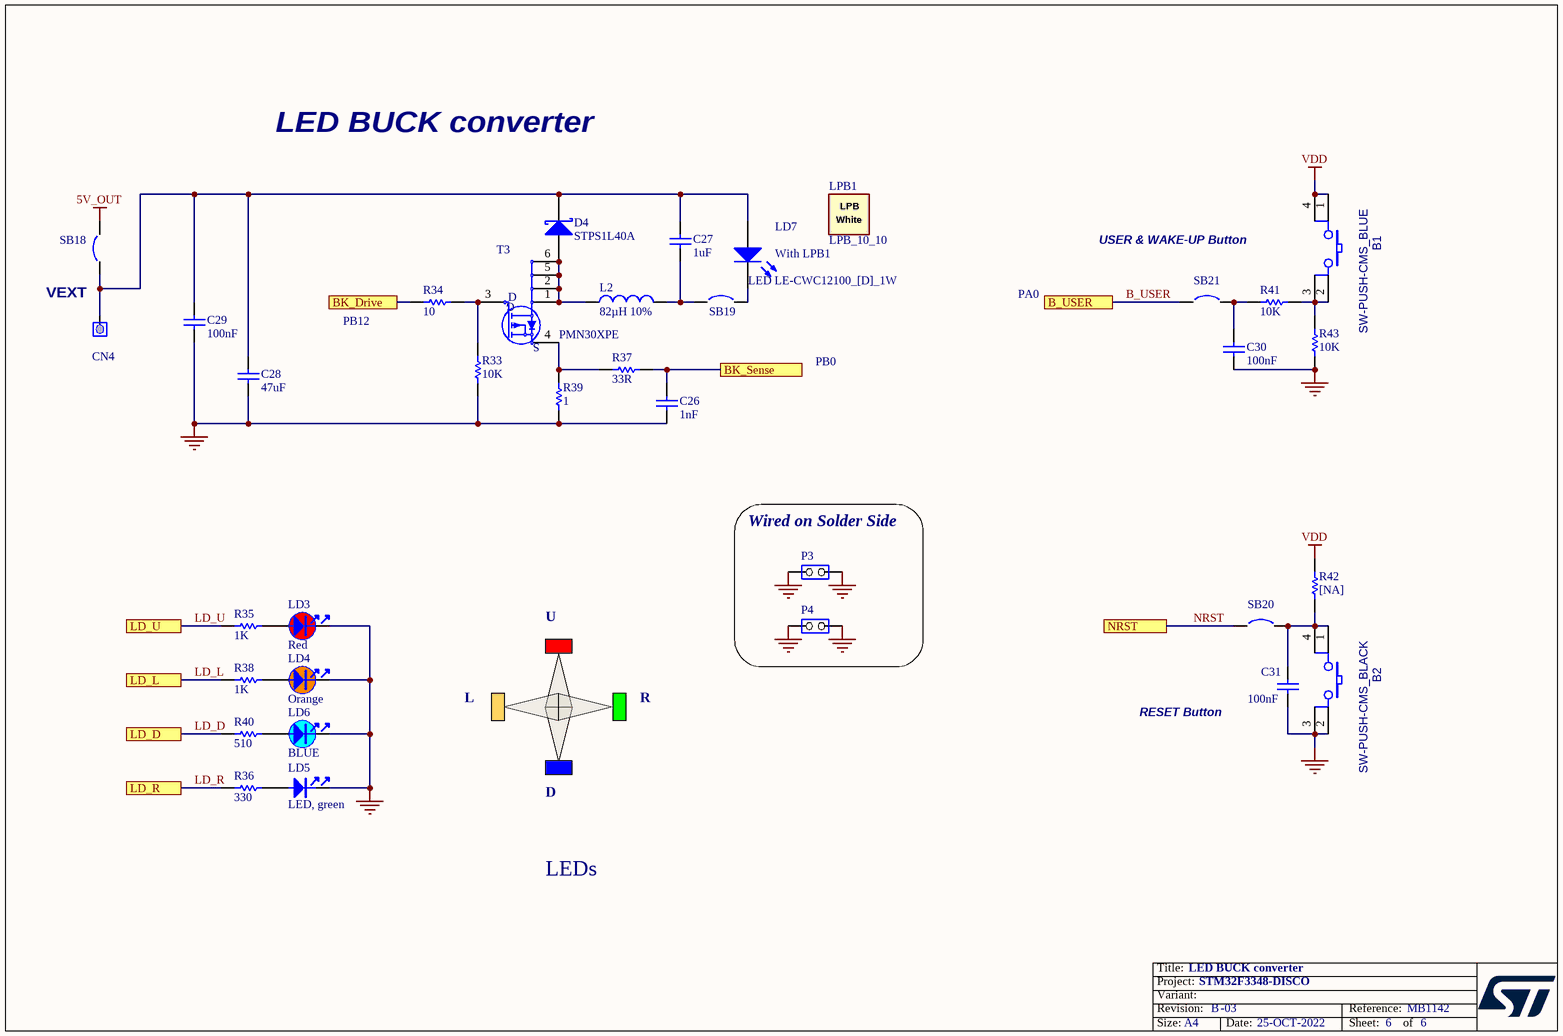
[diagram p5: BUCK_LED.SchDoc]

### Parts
B1  SW-PUSH-CMS_BLUE  [BP1CMS]
B2  SW-PUSH-CMS_BLACK  [BP1CMS]
C26  1nF  [0805C]
C27  1uF  [0805C]
C28  47uF  [1206C]
C29  100nF  [0805C]
C30  100nF  [0402C]
C31  100nF  [0402C]
CN4  Test point 1 pin with hole  [SIP1/2.54]  (value not drawn)
D4  STPS1L40A  [SMA]
L2  82µH 10%  [PSI054T]
LD3  value Red  [LED_0603_RED]  (hidden comment: LED_red)
LD4  value Orange  [LED_0603_ORANGE_H0P4]  (hidden comment: LED_orange)
LD5  LED, green  [0603D]
LD6  value BLUE  [LED_0603_SMD-B_BLUE_H0P4]  (hidden comment: LED_blue)
LD7  LED LE-CWC12100_[D]_1W  [LE-CWC12100]
LPB1  LPB_10_10  [Tbd]
P3  (no value)  [SIP2/2.54]
P4  (no value)  [SIP2/2.54]
R33  10K  [0805]
R34  10  [0805R]
R35  1K  [0603R]
R36  330  [0603R]
R37  33R  [0805R]
R38  1K  [0603R]
R39  1  [1206R]
R40  510  [0603R]
R41  10K  [0402R]
R42  [NA]  [0402R]
R43  10K  [0402R]
SB18  Circuit Breaker  [JP2_SMD]  (value not drawn)
SB19  Circuit Breaker  [JP2_SMD]  (value not drawn)
SB20  Circuit Breaker  [JP2_SMD]  (value not drawn)
SB21  Circuit Breaker  [JP2_SMD]  (value not drawn)
T3  value PMN30XPE  [MOS_TSOP6_CASE-457_P095]  (hidden comment: PMN30XP)

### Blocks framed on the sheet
Wired on Solder Side: P3 P4

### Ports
B_USER, BK_Drive, BK_Sense, LD_D, LD_L, LD_R, LD_U, NRST

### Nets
5V_OUT: SB18.2
GND: B2.2 B2.3 C26.1 C28.1 C29.1 C30.1 C31.1 LD3.2 LD4.2 LD5.2 LD6.2 P3.1(COMMON) P3.2(NO) P4.1(COMMON) P4.2(NO) R33.1 R39.1 R43.1
VDD: B1.1 B1.4 R42.2
B_USER: SB21.1 ; port B_USER
BK_Drive: R34.1 ; port BK_Drive
BK_Sense: C26.2 R37.2 ; port BK_Sense
LD_D: R40.1 ; port LD_D
LD_L: R38.1 ; port LD_L
LD_R: R36.1 ; port LD_R
LD_U: R35.1 ; port LD_U
NRST: SB20.1 ; port NRST
NetB1_2: B1.2 B1.3 R41.2 R43.2
NetB2_1: B2.1 B2.4 C31.2 R42.1 SB20.2
NetC27_1: C27.1 L2.2 SB19.1
NetC27_2: C27.2 C28.2 C29.2 CN4.1(COMMON) D4.2(K) LD7.1(A) SB18.1
NetC30_2: C30.2 R41.1 SB21.2
NetD4_1: D4.1(A) L2.1 T3.1(S) T3.2(S) T3.5(D) T3.6(D)
NetLD3_1: LD3.1 R35.2
NetLD4_1: LD4.1 R38.2
NetLD5_1: LD5.1 R36.2
NetLD6_1: LD6.1 R40.2
NetLD7_2: LD7.2(K) SB19.2
NetR33_2: R33.2 R34.2 T3.3(G)
NetR37_1: R37.1 R39.2 T3.4(S)

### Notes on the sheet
- LED BUCK converter
- USER & WAKE-UP Button
- VEXT
- (near LD7) With LPB1
- PA0
- PB12
- PB0
- U
- L
- R
- RESET Button
- D
- LEDs

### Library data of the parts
B1 = SW-PUSH-CMS_BLUE: Non-Open Push-Button 0.1A 24V; Manuf_2: FARNELL; Manuf_Part_2: 535-930; Manuf_1: wealthmetal; Manuf_Part_1: TD0341X-G01-BLU; Ref St: 9180120
B2 = SW-PUSH-CMS_BLACK: Non-Open Push-Button 0.1A 24V; Manuf_2: FARNELL; Manuf_Part_2: 535-930; Manuf_1: wealthmetal; Manuf_Part_1: TD0341X-G01-BLA; Ref St: 9180120
C26 = Cap_1nF_X7R_10%_0805: Capacitor,1nF,50V,X7R,10%,0805,YAGEO; Order: CC0805KKX7R9BB102
C27 = Cap_1uF_X5R_10%_0805: Capacitor,1uF,16V,X5R,10%,0805,YAGEO; Manuf_Part_1: CC0805KRX5R7BB105
C28 = Cap_47uF_X5R_10%_1206: as C38 on sheet BUCK_BOOST
C29 = Cap_100nF_X7R_10%_0805: as C33 on sheet BUCK_BOOST
C30 C31 = Cap_100nF_X7R_10%_0402: as C2 on sheet ST_LINK_V2
CN4 = TP1: Test Point; Fitted: NO
D4 = STPS1L40A: Low Drop power Schottky rectifier; Manuf_1: STM; Provided: ST; Ref St: xxxxxxxx; ECCN_US/EU: EAR99/NEC
L2 = Ind_82µH_0.65A_10%: as L3 on sheet BUCK_BOOST
LD3 = MCD-02899: as LD1 on sheet ST_LINK_V2
LD4 = MCD-02785: LED, Orange, 2V2, 5mA, 0603; Part_Type: Display; Part_Preference: Recommended; Manufacturer: EVERLIGHT; Manufacturer_Part_Number: 19-217/S2C-AM2N2VY/6T; Full_Alternate_Internal_Part_Number: MCD-00321; Component_Country_Of_Origin: China; ShowFields: YES; ID: 4897
LD5 = LED_green: LED, green, 0603; Manuf_1: everlight; Manuf_Part_1: 19-213SYGC/S530-E2/TR8; ECCN_US/EU: EAR99/NEC
LD6 = MCD-02786: LED, Blue, VF: Min=2.5V, Max=3.1V, 10mA, 0603; Part_Type: Display; Part_Preference: Recommended; Manufacturer: EVERLIGHT; Manufacturer_Part_Number: 19-217/BHC-ZL1M2RY/6T; Full_Alternate_Internal_Part_Number: MCD-01131; Component_Country_Of_Origin: China; ShowFields: YES; ID: 4898
LD7 = LED LE-CWC12100_[D]_1W: LED White LE-CWC12100_[D]_1W, Everluck; ECCN_US/EU: EAR99/NEC
LPB1 = LPB_10_10: LIGHT PIPE BAR 10X10MM WHT DIFF; Manuf_Part_1: LPBS01110101S; Manuf_1: Lumex Opto/Components Inc; Order: 67-1845-ND; Ref St: xxxxxx; Order_2: 2062199
P3 P4 = JP2
R33 R37 = RES SMD 0805 4R7 150V  0.125W: as R45 on sheet BUCK_BOOST
R34 = Res_10_1%_0805: Resistor,10,0805,1%,YAGEO
R35 R36 R38 R40 = Resistor_ST: Resistor 0402 / 0603 / 0805; Value: 10K
R39 = Res_1_1%_1206: Resistor,1,1206,1%,VISHAY; Manuf_Part_1: CRCW12061R00FKEA; Order: 1653087
R41 R43 = Res_10K_1%_0402: Resistor,10K,0402,1%,YAGEO; Manuf_Part_1: RC0402FR-0710KL
R42 = Resistor_ST: Resistor 0402 / 0603 / 0805; Value: 10K; Fitted: NO
SB18-SB21 = Circuit Breaker: Solder: YES
T3 = MCD-03170: as T2 on sheet ST_LINK_V2

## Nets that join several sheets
3V: Top (P2.1), ST_LINK_V2 (5 pins)
5V_IN: Top (P1.1), ST_LINK_V2 (D2.1 R17.2)
5V_OUT: Top (P1.3), ST_LINK_V2 (8 pins), BUCK_LED (SB18.2)
GND: Top (5 pins), ST_LINK_V2 (41 pins), STM32Fx (13 pins), BUCK_BOOST (26 pins), BUCK_LED (18 pins)
VDD: Top (P2.5), ST_LINK_V2 (JP3.2), STM32Fx (9 pins), BUCK_LED (B1.1 B1.4 R42.2)
B_USER: STM32Fx (U4.10), BUCK_LED (SB21.1)
BK_Drive: STM32Fx (U4.25), BUCK_LED (R34.1)
BK_Sense: STM32Fx (U4.18), BUCK_LED (C26.2 R37.2)
LD_D: STM32Fx (U4.43), BUCK_LED (R40.1)
LD_L: STM32Fx (U4.45), BUCK_LED (R38.1)
LD_R: STM32Fx (U4.46), BUCK_LED (R36.1)
LD_U: STM32Fx (U4.42), BUCK_LED (R35.1)
MCO: ST_LINK_V2 (C40.1 R65.2), STM32Fx (SB12.1)
N1_Drive: STM32Fx (U4.30), BUCK_BOOST (R56.1)
N2_Drive: STM32Fx (U4.31), BUCK_BOOST (R57.2)
NRST: ST_LINK_V2 (SB11.2), STM32Fx (U4.7), BUCK_LED (SB20.1)
P1_Drive: STM32Fx (U4.29), BUCK_BOOST (R55.1 R61.1)
P2_Drive: STM32Fx (U4.32), BUCK_BOOST (R58.2 R64.2)
PA1: STM32Fx (U4.11), BUCK_BOOST (C32.2 R45.2 R51.1)
PA3: STM32Fx (U4.13), BUCK_BOOST (C35.2 R44.2 R46.2 R52.2)
PA13: ST_LINK_V2 (SB10.1), STM32Fx (U4.34)
PA14: ST_LINK_V2 (SB5.1), STM32Fx (U4.37)
PB3: ST_LINK_V2 (SB16.1 SB17.2), STM32Fx (U4.39)
PB4: ST_LINK_V2 (SB14.1), STM32Fx (U4.40)
PB14: STM32Fx (U4.27), BUCK_BOOST (R32.1)

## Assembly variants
F334: not fitted C20 C21 C35 C40 CN4 CN6 JP1 JP2 JP4 R1 R25 R29 R30 R42 R44 R64 SB2 SB4 SB6 SB7 SB9 SB13 SB15 SB17 T15 TP1 TP2 TP3 TP4 X2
